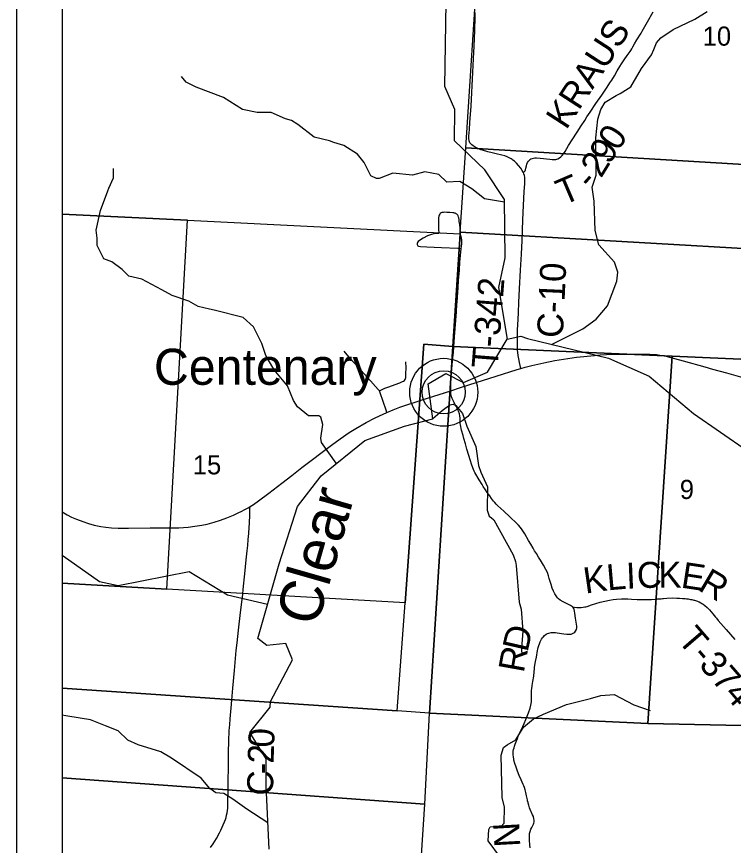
# Model space of a CAD drawing. Extents: x 21.4 to 65.3, y 4 to 26.
# Drawn here: x 23.447 to 25.016, y 22.248 to 24.062 of the extents above; entities that cross this region are included whole.
import ezdxf

# ---------------------------------------------------------------- set-up
doc = ezdxf.new("R2010")
doc.units = 0
for name, color, linetype in [('Default', 7, 'Continuous'), ('GM_X_County_Road', 7, 'Continuous'), ('GM_X_County_Road_Text', 7, 'Continuous'), ('GM_X_Minor_River', 7, 'Continuous'), ('GM_X_Minor_River_Text', 7, 'Continuous'), ('GM_X_Section', 7, 'Continuous'), ('GM_X_Section_Text', 7, 'Continuous'), ('GM_X_State_Route', 7, 'Continuous'), ('GM_X_Township_Road', 7, 'Continuous'), ('GM_X_Township_Road_Text', 7, 'Continuous'), ('GM_X_Unincorporated', 7, 'Continuous'), ('GM_X_Unincorporated_Location', 7, 'Continuous'), ('GM_X_Unincorporated_Text', 7, 'Continuous'), ('SH_Cut_Line', 7, 'Continuous'), ('SH_Data', 7, 'Continuous')]:
    doc.layers.add(name, color=color, linetype=linetype)

msp = doc.modelspace()

# ---------------------------------------------------------------- linework, layer by layer
at = {"layer": 'Default'}
msp.add_lwpolyline([(26.3906, 21.3613), (26.4573, 22.45), (26.4915, 22.9722), (26.4968, 23.0532), (26.5076, 23.2181), (26.5201, 23.4302), (26.5253, 23.5099), (26.571, 24.2838), (26.5714, 24.2916), (26.5716, 24.3007), (26.5721, 24.3116), (26.5728, 24.3278), (26.5729, 24.3421), (26.5729, 24.3464), (26.5731, 24.3575), (26.5731, 24.358), (26.5731, 24.3616), (26.5731, 24.3659), (26.5732, 24.3694), (26.5734, 24.3737), (26.5741, 24.3781), (26.6018, 24.8542), (23.5473, 24.8542), (23.5473, 20.5568)], dxfattribs=at)
for points in [[(23.5473, 24.6641), (23.5473, 23.6293), (23.8211, 23.6164), (24.4175, 23.5863), (24.4178, 23.5899), (24.4301, 23.7749), (24.457, 24.1912), (24.4839, 24.6087)], [(23.5473, 23.6293), (23.5473, 22.8217), (23.7762, 22.8091), (23.8211, 23.6164)], [(23.5473, 22.8217), (23.5473, 22.5923), (24.2802, 22.5424), (24.2972, 22.7792), (23.7762, 22.8091)], [(23.5473, 22.5923), (23.5473, 22.3957), (24.3404, 22.3383), (24.3505, 22.5376), (24.2802, 22.5424)], [(23.5473, 22.3957), (23.5473, 21.9832), (24.3136, 21.9252), (24.3404, 22.3383)]]:
    msp.add_lwpolyline(points, close=True, dxfattribs=at)
at = {"layer": 'GM_X_County_Road'}
for points in [[(24.5315, 23.7492), (24.529, 23.7509), (24.5251, 23.753), (24.5205, 23.7551), (24.5151, 23.7569), (24.5091, 23.7585), (24.4963, 23.7614), (24.4874, 23.7635), (24.4786, 23.7657), (24.4665, 23.7695), (24.463, 23.7707), (24.4567, 23.7732), (24.4534, 23.7747), (24.4505, 23.7762), (24.446, 23.7789), (24.443, 23.7812), (24.4408, 23.7833), (24.439, 23.7856), (24.4379, 23.7876), (24.4371, 23.7902), (24.4367, 23.795), (24.4368, 23.7999), (24.438, 23.8148), (24.4391, 23.8302), (24.4415, 23.8656), (24.4456, 23.9401), (24.4477, 23.9841), (24.4483, 23.9965), (24.4498, 24.0319), (24.4506, 24.0605), (24.4504, 24.071)], [(24.5505, 23.2921), (24.5488, 23.2981), (24.5473, 23.305), (24.5458, 23.3129), (24.5447, 23.3201), (24.5439, 23.3268), (24.5435, 23.3317), (24.5433, 23.3361), (24.5431, 23.3412), (24.5431, 23.3677), (24.5433, 23.3764), (24.5443, 23.3994), (24.545, 23.4143), (24.5461, 23.4366), (24.5476, 23.4658), (24.5497, 23.5067), (24.5516, 23.5421), (24.5532, 23.5719), (24.5551, 23.6172), (24.5566, 23.6488), (24.5581, 23.6792), (24.559, 23.696), (24.5594, 23.7041), (24.5592, 23.7098), (24.5584, 23.7142), (24.5573, 23.7178), (24.5561, 23.7204), (24.5557, 23.7213), (24.5536, 23.7252), (24.5504, 23.7299), (24.5453, 23.7362), (24.5407, 23.7414), (24.5366, 23.7453), (24.5332, 23.7481), (24.5315, 23.7492)], [(23.9407, 22.7859), (23.9413, 22.7908), (23.9439, 22.8156), (23.946, 22.8359), (23.9474, 22.8498), (23.949, 22.8655), (23.9505, 22.8797), (23.9518, 22.8928), (23.9529, 22.9044), (23.9542, 22.9179), (23.9554, 22.9305), (23.9565, 22.9446), (23.9571, 22.9528), (23.9579, 22.9721), (23.9579, 22.9841), (23.958, 22.9897)], [(23.8712, 22.2433), (23.8774, 22.2519), (23.8847, 22.2635), (23.8914, 22.2755), (23.8945, 22.2818), (23.8974, 22.2878), (23.8996, 22.2932), (23.9023, 22.2999), (23.904, 22.3049), (23.9055, 22.3094), (23.9067, 22.3144), (23.9079, 22.3191), (23.9085, 22.3244), (23.9092, 22.3296), (23.9095, 22.3383), (23.9097, 22.3452), (23.9098, 22.3526), (23.91, 22.3601), (23.9103, 22.3893), (23.9107, 22.4185), (23.9108, 22.429), (23.9108, 22.4409), (23.9109, 22.4505), (23.911, 22.4607), (23.9113, 22.4676), (23.9115, 22.4745), (23.9118, 22.4843), (23.9122, 22.4918), (23.9127, 22.4991), (23.9132, 22.5062), (23.9137, 22.5121), (23.9147, 22.5251), (23.9166, 22.5492), (23.918, 22.5659), (23.9204, 22.5919), (23.9238, 22.6309), (23.9263, 22.6575), (23.928, 22.6748), (23.9297, 22.6915), (23.933, 22.7192), (23.9374, 22.7581), (23.9407, 22.7859)]]:
    msp.add_lwpolyline(points, dxfattribs=at)
at = {"layer": 'GM_X_Minor_River'}
for points in [[(24.521, 23.3563), (24.5022, 23.4691), (24.5165, 23.5341), (24.5149, 23.6613), (24.4719, 23.7265), (24.4054, 23.7901), (24.406, 23.8584), (24.3844, 23.9087), (24.3873, 24.0927), (24.385, 24.1568), (24.3406, 24.2931), (24.319, 24.497), (24.2627, 24.6502), (24.2202, 24.7075), (24.0286, 24.7795), (24.0144, 24.7922), (23.9767, 24.8306), (23.8365, 24.8445), (23.6501, 24.729), (23.6289, 24.7193)], [(24.6178, 23.3444), (24.6859, 23.3783), (24.7155, 23.3996), (24.7398, 23.4289), (24.7603, 23.4826), (24.7629, 23.5023), (24.7557, 23.5247), (24.7209, 23.5627), (24.7129, 23.5935), (24.7107, 23.6577), (24.7065, 23.6889), (24.7152, 23.7148), (24.7145, 23.7965), (24.7187, 23.8376), (24.7252, 23.8589), (24.735, 23.8745), (24.7589, 23.8889), (24.7676, 23.8939), (24.7911, 23.9083), (24.8143, 23.9487), (24.8363, 23.978), (24.8412, 23.9897), (24.8469, 24.0046), (24.8564, 24.0152), (24.884, 24.0339), (24.9311, 24.0564), (24.958, 24.0731)], [(24.5149, 23.6559), (24.4707, 23.6632), (24.4434, 23.6848), (24.4169, 23.7011), (24.3885, 23.6996), (24.3714, 23.7167), (24.3407, 23.722), (24.3138, 23.7147), (24.2702, 23.7192), (24.2406, 23.7078), (24.2346, 23.7074), (24.2221, 23.7135), (24.2077, 23.7424), (24.1933, 23.761), (24.1633, 23.7796), (24.141, 23.7864), (24.1319, 23.7898), (24.0985, 23.7981), (24.0629, 23.8258), (24.0485, 23.8349), (24.0356, 23.8383), (24.0045, 23.8524), (23.9738, 23.8523), (23.9416, 23.8588), (23.9003, 23.885), (23.84, 23.9073), (23.8181, 23.9183), (23.8078, 23.9312)], [(24.1468, 23.0848), (24.1142, 23.1298), (24.1127, 23.1393), (24.1173, 23.169), (24.1131, 23.1853), (24.1082, 23.188), (24.0858, 23.188), (24.0619, 23.2081), (24.0528, 23.2221), (24.04, 23.2541), (24.0108, 23.289), (23.9926, 23.3205), (23.9839, 23.3468), (23.9653, 23.3832), (23.943, 23.4034), (23.8797, 23.4192), (23.8694, 23.4215), (23.8448, 23.4272), (23.8243, 23.439), (23.7879, 23.4515), (23.7648, 23.464), (23.7216, 23.4871), (23.6928, 23.4939), (23.678, 23.5087), (23.6557, 23.5254), (23.6379, 23.5319), (23.6238, 23.5608), (23.6238, 23.5771), (23.6216, 23.5942), (23.6311, 23.6376), (23.647, 23.6809), (23.6489, 23.6866), (23.6595, 23.7091), (23.6595, 23.7296)], [(23.9998, 22.2402), (23.9934, 22.3787), (23.9934, 22.4375), (23.9577, 22.4953), (24.0018, 22.5503), (24.0028, 22.5629), (24.0513, 22.6544), (24.036, 22.6899), (23.9947, 22.6858), (23.9748, 22.7012), (24.0216, 22.864), (24.0621, 22.9896), (24.1136, 23.0569), (24.2094, 23.134), (24.2963, 23.1659), (24.3579, 23.1817), (24.3478, 23.2586), (24.3866, 23.281), (24.4252, 23.2612), (24.4777, 23.2837), (24.5204, 23.3562), (24.5503, 23.3622), (24.5648, 23.3577), (24.7419, 23.3142), (24.8309, 23.2751), (24.9284, 23.1936), (25.1054, 23.0707)], [(24.3578, 23.1824), (24.3784, 23.2001), (24.3951, 23.2122), (24.4023, 23.2141), (24.4084, 23.2111), (24.4232, 23.1936), (24.4326, 23.1659), (24.4523, 23.1214), (24.458, 23.0796), (24.4629, 23.0652), (24.4773, 23.0325), (24.4769, 22.9816), (24.4815, 22.9686), (24.4864, 22.9648), (24.4917, 22.9603), (24.5338, 22.8839), (24.5387, 22.8695), (24.5402, 22.8607), (24.547, 22.7801), (24.5515, 22.7653), (24.5545, 22.7166), (24.5519, 22.6801), (24.5523, 22.6627)], [(23.9961, 22.7755), (23.9086, 22.7958), (23.8248, 22.8471), (23.6699, 22.8161), (23.6284, 22.8252), (23.5495, 22.8814), (23.5473, 22.8843)], [(24.5062, 22.2216), (24.4793, 22.258), (24.4805, 22.2831), (24.4835, 22.2885), (24.4899, 22.2896), (24.507, 22.2889), (24.5138, 22.2965), (24.5146, 22.3315), (24.5093, 22.3531), (24.5071, 22.4455), (24.5128, 22.4626), (24.5207, 22.468), (24.5393, 22.4794), (24.556, 22.5072), (24.578, 22.5254), (24.6, 22.535), (24.65, 22.5567), (24.7027, 22.5697), (24.7255, 22.5765), (24.7546, 22.5781), (24.7979, 22.5561), (24.8335, 22.5436)], [(23.9972, 22.2972), (23.9513, 22.3274), (23.9206, 22.3491), (23.9005, 22.3616), (23.8835, 22.3635), (23.8698, 22.3726), (23.8512, 22.395), (23.7864, 22.439), (23.7626, 22.4527), (23.7133, 22.4679), (23.6905, 22.4785), (23.6697, 22.499), (23.642, 22.5096), (23.6091, 22.5229), (23.5598, 22.5312), (23.5552, 22.5319), (23.5473, 22.5333)]]:
    msp.add_lwpolyline(points, dxfattribs=at)
at = {"layer": 'GM_X_Section'}
for points in [[(25.5145, 24.1345), (25.4893, 23.7114), (24.4301, 23.7749), (24.457, 24.1912)], [(24.4301, 23.7749), (25.4893, 23.7114), (25.4788, 23.5287), (24.4178, 23.5899)], [(23.8211, 23.6164), (24.4175, 23.5863), (24.4019, 23.3397), (24.338, 23.345), (24.2972, 22.7792), (23.7762, 22.8091)], [(24.4175, 23.5863), (24.4178, 23.5899), (25.4788, 23.5287), (25.4647, 23.2936), (24.8812, 23.3189), (24.4019, 23.3397)], [(24.4019, 23.3397), (24.3505, 22.5376), (24.2802, 22.5424), (24.2972, 22.7792), (24.338, 23.345)], [(24.8812, 23.3189), (24.828, 22.5152), (24.3505, 22.5376), (24.4019, 23.3397)], [(25.4647, 23.2936), (25.4085, 22.5025), (24.828, 22.5152), (24.8812, 23.3189)], [(24.3505, 22.5376), (24.828, 22.5152), (25.4085, 22.5025), (25.3384, 21.4821), (24.7985, 21.5074), (24.2858, 21.5075), (24.3136, 21.9252), (24.3404, 22.3383)]]:
    msp.add_lwpolyline(points, close=True, dxfattribs=at)
at = {"layer": 'GM_X_State_Route'}
for points in [[(23.9389, 22.9792), (23.9469, 22.9832), (23.9539, 22.9871), (23.958, 22.9897), (23.9654, 22.9945), (23.9767, 23.0024), (23.9992, 23.0191), (24.0277, 23.0411), (24.0495, 23.0576), (24.0716, 23.0748), (24.1363, 23.1242), (24.1553, 23.1382), (24.1751, 23.152), (24.1893, 23.1608), (24.212, 23.1737), (24.2318, 23.1839), (24.2492, 23.192), (24.2574, 23.1955), (24.2715, 23.2015), (24.286, 23.207), (24.3349, 23.2233), (24.3973, 23.2432), (24.4187, 23.25), (24.4525, 23.2614), (24.4964, 23.2752), (24.5421, 23.2898), (24.5505, 23.2921), (24.5596, 23.2946), (24.5742, 23.2983), (24.6009, 23.3044), (24.6247, 23.3091), (24.6534, 23.3139), (24.6719, 23.3164), (24.7114, 23.3206), (24.7241, 23.3217), (24.738, 23.3224), (24.7585, 23.3231), (24.81, 23.3234), (24.8323, 23.3229), (24.8472, 23.3221), (24.8545, 23.321), (24.8685, 23.3186), (24.8757, 23.3169), (24.9057, 23.3089), (24.9528, 23.2954), (24.9701, 23.2905), (25.0006, 23.282), (25.0358, 23.2719)], [(23.5473, 22.9782), (23.5583, 22.9716), (23.5677, 22.9667), (23.5785, 22.9618), (23.5919, 22.9566), (23.6043, 22.9526), (23.617, 22.9492), (23.6316, 22.9462), (23.6427, 22.9445), (23.6551, 22.9432), (23.6694, 22.9424), (23.6924, 22.9422), (23.7396, 22.9429), (23.7608, 22.943), (23.785, 22.943), (23.8024, 22.9433), (23.8229, 22.9448), (23.8372, 22.9464), (23.8525, 22.9489), (23.8641, 22.9514), (23.8798, 22.9554), (23.8935, 22.9596), (23.9075, 22.9647), (23.9218, 22.9708), (23.9336, 22.9764), (23.9389, 22.9792)]]:
    msp.add_lwpolyline(points, dxfattribs=at)
at = {"layer": 'GM_X_Township_Road'}
for points in [[(24.5693, 23.7477), (24.5705, 23.7489), (24.5726, 23.7503), (24.5749, 23.7513), (24.5779, 23.7522), (24.581, 23.7525), (24.5848, 23.7526), (24.5928, 23.752), (24.6137, 23.7498), (24.6192, 23.7493), (24.6236, 23.7492), (24.6267, 23.7494), (24.6294, 23.7499), (24.6317, 23.7507), (24.6354, 23.7527), (24.638, 23.7548), (24.6408, 23.7578), (24.6439, 23.7616), (24.6473, 23.767), (24.651, 23.7732), (24.6549, 23.7796), (24.6631, 23.7921), (24.6738, 23.8088), (24.6828, 23.8229), (24.6901, 23.8345), (24.6951, 23.8423), (24.7019, 23.8527), (24.7147, 23.8716), (24.7275, 23.8899), (24.7394, 23.9073), (24.7455, 23.9167), (24.7494, 23.923), (24.7551, 23.9326), (24.7614, 23.9434), (24.7669, 23.9524), (24.7705, 23.9582), (24.7764, 23.967), (24.7833, 23.9765), (24.7897, 23.9854), (24.7914, 23.988), (24.7934, 23.9917), (24.7958, 23.9959), (24.7994, 24.0023), (24.8045, 24.0109), (24.8134, 24.0258), (24.8159, 24.0301), (24.8276, 24.0506), (24.84, 24.0721)], [(24.5561, 23.7204), (24.5577, 23.7219), (24.5597, 23.7244), (24.5604, 23.7263), (24.5616, 23.7302), (24.5629, 23.7354), (24.5639, 23.739), (24.5654, 23.7425), (24.567, 23.7452), (24.5686, 23.7472), (24.5693, 23.7477)], [(24.4202, 23.5543), (24.4206, 23.5585), (24.4213, 23.5652), (24.4215, 23.5676), (24.4216, 23.5704), (24.4213, 23.5731), (24.421, 23.5755), (24.4207, 23.5773), (24.4202, 23.5794), (24.4197, 23.5807), (24.4191, 23.5824), (24.4187, 23.5842), (24.4182, 23.588), (24.4181, 23.5903), (24.4174, 23.599), (24.4167, 23.6067), (24.4159, 23.6132), (24.4152, 23.6176), (24.4146, 23.6213), (24.4142, 23.623), (24.4131, 23.6258), (24.4124, 23.6271), (24.4102, 23.6295), (24.4093, 23.6302), (24.408, 23.6309), (24.407, 23.6315), (24.4056, 23.6319), (24.404, 23.6323), (24.4019, 23.6327), (24.3951, 23.6332), (24.3919, 23.6333), (24.3889, 23.6333), (24.3829, 23.6336), (24.3809, 23.6335), (24.3778, 23.6331), (24.3765, 23.6327), (24.3743, 23.6313), (24.3729, 23.6298), (24.3716, 23.6276), (24.371, 23.6251), (24.3707, 23.6216), (24.3706, 23.6178), (24.3706, 23.6117), (24.3705, 23.5943), (24.3708, 23.5905), (24.371, 23.5884), (24.371, 23.5877), (24.3705, 23.587), (24.3693, 23.5869), (24.3685, 23.5871), (24.3664, 23.5875), (24.3651, 23.5876), (24.364, 23.5875), (24.3629, 23.5874), (24.36, 23.5868), (24.3549, 23.5852), (24.3465, 23.582), (24.337, 23.5769), (24.3288, 23.5717), (24.3262, 23.5698), (24.3244, 23.5679), (24.3237, 23.5654), (24.3238, 23.5634), (24.3246, 23.5615), (24.3254, 23.5604), (24.3269, 23.5592), (24.3306, 23.5585), (24.3445, 23.558), (24.3769, 23.5567), (24.4123, 23.5549), (24.4202, 23.5543)], [(24.4108, 23.4325), (24.411, 23.4365), (24.4117, 23.4483), (24.4131, 23.4686), (24.4142, 23.4841), (24.416, 23.5069), (24.4173, 23.5242), (24.4194, 23.5464), (24.4202, 23.5543)], [(24.3973, 23.2432), (24.3972, 23.2511), (24.3973, 23.2611), (24.3978, 23.2709), (24.3985, 23.2821), (24.4004, 23.2991), (24.4013, 23.3084), (24.4029, 23.3276), (24.4057, 23.361), (24.4096, 23.4157), (24.4108, 23.4325)], [(24.2574, 23.1955), (24.2557, 23.2003), (24.2424, 23.2382), (24.2409, 23.243), (24.238, 23.246), (24.2324, 23.2526), (24.2218, 23.2648), (24.2005, 23.2881), (24.178, 23.313), (24.164, 23.3296)], [(24.2409, 23.243), (24.2459, 23.2453), (24.2532, 23.2484), (24.2592, 23.2508), (24.2859, 23.2607), (24.2915, 23.263), (24.2941, 23.2644), (24.2959, 23.2658), (24.2973, 23.2675), (24.2982, 23.2696), (24.2987, 23.2724), (24.2991, 23.2763), (24.2992, 23.2798), (24.2995, 23.2931), (24.2992, 23.3064)], [(24.5309, 22.9628), (24.5235, 22.9698), (24.5162, 22.9765), (24.513, 22.9794), (24.5002, 22.9912), (24.4962, 22.9951), (24.4933, 22.9983), (24.4906, 23.0016), (24.4862, 23.0075), (24.4823, 23.0131), (24.477, 23.0207), (24.4734, 23.0259), (24.4683, 23.0336), (24.4657, 23.0378), (24.4591, 23.0484), (24.4572, 23.0516), (24.4518, 23.0607), (24.45, 23.064), (24.4483, 23.0672), (24.4466, 23.0711), (24.4455, 23.0742), (24.4444, 23.0769), (24.4431, 23.0804), (24.4395, 23.0916), (24.4364, 23.1017), (24.4325, 23.1154), (24.4293, 23.1269), (24.4261, 23.1383), (24.4242, 23.1453), (24.4207, 23.1572), (24.42, 23.1604), (24.4189, 23.165), (24.4184, 23.1686), (24.4179, 23.1717), (24.4175, 23.1829), (24.417, 23.1879), (24.416, 23.1928), (24.4142, 23.1982), (24.4127, 23.2014), (24.4112, 23.205), (24.4088, 23.2093), (24.4064, 23.2138), (24.4045, 23.2171), (24.4021, 23.2215), (24.4001, 23.2259), (24.3988, 23.2297), (24.3978, 23.2337), (24.3974, 23.2363), (24.3973, 23.2387), (24.3973, 23.2432)], [(24.6634, 22.7704), (24.6613, 22.7717), (24.6592, 22.773), (24.643, 22.7812), (24.6368, 22.785), (24.6329, 22.7877), (24.6304, 22.79), (24.6274, 22.7941), (24.6246, 22.7987), (24.6218, 22.8047), (24.6193, 22.8107), (24.6166, 22.819), (24.6127, 22.8323), (24.6108, 22.8384), (24.6085, 22.8452), (24.6054, 22.8522), (24.6003, 22.8614), (24.5934, 22.8725), (24.5892, 22.8792), (24.5844, 22.8867), (24.5805, 22.8929), (24.5772, 22.8983), (24.5723, 22.9071), (24.5675, 22.9156), (24.5591, 22.9302), (24.5537, 22.9386), (24.55, 22.9436), (24.5455, 22.9487), (24.537, 22.957), (24.5309, 22.9628)], [(24.6634, 22.7704), (24.668, 22.7696), (24.6726, 22.7689), (24.6779, 22.7685), (24.6825, 22.7688), (24.6871, 22.7693), (24.6906, 22.7699), (24.6924, 22.7703), (24.6953, 22.7711), (24.705, 22.7746), (24.7142, 22.7778), (24.7237, 22.7806), (24.7345, 22.7829), (24.7442, 22.7847), (24.7522, 22.7861), (24.7595, 22.787), (24.7706, 22.7878), (24.7755, 22.7879), (24.7847, 22.7876), (24.7925, 22.787), (24.8052, 22.7861), (24.8163, 22.786), (24.8261, 22.7863), (24.8362, 22.7866), (24.8442, 22.787), (24.8485, 22.7874), (24.8572, 22.788), (24.8603, 22.7883), (24.8627, 22.7885), (24.8695, 22.789), (24.8819, 22.7897), (24.8918, 22.7895), (24.8973, 22.7892), (24.9041, 22.7888), (24.9103, 22.7882), (24.9127, 22.788), (24.9163, 22.7874), (24.9218, 22.7866), (24.9242, 22.7861), (24.927, 22.7857), (24.9287, 22.7851), (24.9305, 22.7847), (24.9351, 22.7833), (24.9403, 22.7813), (24.944, 22.7791), (24.9467, 22.7777), (24.9497, 22.7757), (24.9531, 22.7731), (24.9582, 22.7685), (24.9629, 22.7637), (24.9665, 22.7595), (24.9704, 22.7546), (24.9733, 22.7514), (24.9764, 22.7476), (24.9785, 22.7454), (24.9824, 22.7405), (24.9993, 22.7209), (25.0185, 22.6989)], [(24.5711, 22.2426), (24.5702, 22.2495), (24.5699, 22.2526), (24.5696, 22.2563), (24.5691, 22.2643), (24.5691, 22.2686), (24.5695, 22.2741), (24.5707, 22.2788), (24.5726, 22.2833), (24.5743, 22.287), (24.577, 22.2915), (24.5783, 22.2948), (24.579, 22.2968), (24.5794, 22.2994), (24.5796, 22.3012), (24.5794, 22.3036), (24.5792, 22.3062), (24.5779, 22.3111), (24.5762, 22.3151), (24.571, 22.3264), (24.5696, 22.33), (24.5685, 22.3334), (24.5676, 22.3363), (24.5666, 22.3404), (24.5662, 22.3422), (24.5653, 22.3458), (24.5649, 22.3476), (24.5643, 22.3506), (24.563, 22.3567), (24.5615, 22.364), (24.5599, 22.37), (24.5584, 22.3748), (24.5569, 22.3787), (24.5556, 22.3817), (24.5512, 22.3918), (24.5471, 22.4008), (24.543, 22.4109), (24.5402, 22.4192), (24.5375, 22.4271), (24.5355, 22.4346), (24.5348, 22.4379), (24.5342, 22.4413), (24.5338, 22.4468), (24.5337, 22.4498), (24.534, 22.4541), (24.5347, 22.4583), (24.5357, 22.4617), (24.5367, 22.4653), (24.5381, 22.4693), (24.5396, 22.4733), (24.5428, 22.482), (24.5448, 22.4872), (24.5467, 22.4917), (24.5547, 22.5085), (24.5575, 22.5147), (24.5614, 22.5238), (24.5672, 22.5382), (24.5706, 22.5481), (24.5724, 22.5553), (24.5736, 22.5626), (24.5738, 22.5654), (24.574, 22.5688), (24.5739, 22.5724), (24.5737, 22.5756), (24.5735, 22.5812), (24.5738, 22.5852), (24.574, 22.5879), (24.5743, 22.5904), (24.5747, 22.5934), (24.575, 22.5952), (24.5751, 22.5967), (24.5754, 22.5983), (24.576, 22.6024), (24.5767, 22.6065), (24.5773, 22.6106), (24.5779, 22.6146), (24.5786, 22.6185), (24.5791, 22.6211), (24.5795, 22.6252), (24.5806, 22.6374), (24.5813, 22.6422), (24.5826, 22.6509), (24.5845, 22.6601), (24.587, 22.6745), (24.5875, 22.6775), (24.5883, 22.6812), (24.5889, 22.6832), (24.5898, 22.6857), (24.5912, 22.6891), (24.5931, 22.6935), (24.5938, 22.6952), (24.596, 22.6995), (24.5975, 22.7022), (24.599, 22.7041), (24.6019, 22.7072), (24.6057, 22.7102), (24.609, 22.7118), (24.6118, 22.7128), (24.6166, 22.7137), (24.6228, 22.7139), (24.6264, 22.7137), (24.6302, 22.7134), (24.6443, 22.7113), (24.6511, 22.7103), (24.6568, 22.7101), (24.6606, 22.7107), (24.6636, 22.7117), (24.6664, 22.7132), (24.6684, 22.7149), (24.6704, 22.7173), (24.672, 22.7209), (24.6727, 22.724), (24.6728, 22.7278), (24.6724, 22.7322), (24.6703, 22.7455), (24.6686, 22.7567), (24.6681, 22.7604), (24.6673, 22.7646), (24.6665, 22.7669), (24.6651, 22.7688), (24.6634, 22.7704)]]:
    msp.add_lwpolyline(points, dxfattribs=at)
at = {"layer": 'GM_X_Unincorporated'}
for radius in [0.0744, 0.0472]:
    msp.add_circle((24.3817, 23.2397), radius, dxfattribs=at)
at = {"layer": 'GM_X_Unincorporated_Location'}
msp.add_line((24.3817, 23.2397), (24.3817, 23.2397), dxfattribs=at)
at = {"layer": 'SH_Cut_Line'}
msp.add_lwpolyline([(29.9103, 24.8542), (23.5473, 24.8542), (23.5473, 18.0542)], dxfattribs=at)
at = {"layer": 'SH_Data'}
for p, q in [((23.4473, 24.9542), (23.4473, 17.9542)), ((23.5473, 24.8542), (23.5473, 18.0542))]:
    msp.add_line(p, q, dxfattribs=at)

# ---------------------------------------------------------------- texts
at = {"layer": 'GM_X_County_Road_Text'}
for s, height, rotation, p in [('C-10', 0.05682, 87.3274, (24.6423, 23.3577)), ('0', 0.0568, 87.418, (24.0105, 22.4613)), ('2', 0.0568, 88.5636, (24.0096, 22.4266)), ('-', 0.0568, 88.7743, (24.0091, 22.4033)), ('C', 0.0568, 88.8251, (24.0082, 22.3567))]:
    msp.add_text(s, height=height, rotation=rotation, dxfattribs=at).set_placement(p)
at = {"layer": 'GM_X_Minor_River_Text'}
msp.add_text('Clear', height=0.09469, rotation=73.9989, dxfattribs=at).set_placement((24.1044, 22.7242))
at = {"layer": 'GM_X_Section_Text'}
for s, height, p in [('10', 0.04186, (24.9482, 23.9983)), ('15', 0.04186, (23.8328, 23.0601)), ('9', 0.0419, (24.8982, 23.0062))]:
    msp.add_text(s, height=height, rotation=0, dxfattribs=at).set_placement(p)
at = {"layer": 'GM_X_Township_Road_Text'}
for s, height, rotation, p in [('KRAUS', 0.05682, 57.0662, (24.6498, 23.8124)), ('0', 0.0568, 56.9277, (24.7631, 23.7656)), ('9', 0.0568, 57.0734, (24.7441, 23.7363)), ('2', 0.0568, 58.3651, (24.726, 23.7068)), ('T', 0.0568, 23.1688, (24.6431, 23.6481)), ('-', 0.0568, 48.5922, (24.7042, 23.6808)), ('T-342', 0.05682, 85.5174, (24.4993, 23.2906)), ('K', 0.0568, 8.2537, (24.6916, 22.7991)), ('L', 0.0568, 5.0509, (24.7403, 22.8061)), ('I', 0.0568, 2.4909, (24.7819, 22.8098)), ('C', 0.0568, 1.8972, (24.8051, 22.8108)), ('K', 0.0568, 0.1056, (24.8513, 22.8124)), ('E', 0.0568, 351.3487, (24.899, 22.8126)), ('R', 0.0568, 329.4519, (24.9356, 22.8082)), ('D', 0.0568, 77.1353, (24.565, 22.6694)), ('T-374', 0.05682, 310.6916, (24.8914, 22.6969)), ('R', 0.0568, 79.7311, (24.5568, 22.6242)), ('N', 0.0568, 93.1707, (24.5495, 22.2455))]:
    msp.add_text(s, height=height, rotation=rotation, dxfattribs=at).set_placement(p)
at = {"layer": 'GM_X_Unincorporated_Text'}
msp.add_text('Centenary', height=0.07898, rotation=0, dxfattribs=at).set_placement((23.7478, 23.2561))

doc.saveas('drawing.dxf')
